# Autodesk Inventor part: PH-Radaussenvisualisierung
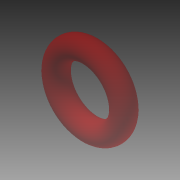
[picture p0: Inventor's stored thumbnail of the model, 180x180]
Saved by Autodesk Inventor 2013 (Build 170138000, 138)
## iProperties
Created: 2012-07
Part Number: PH-Radaussenvisualisierung
Material: Rot - Durchsichtig
Document SubType Name: Modeling
Designer: rYan
Mass: 13.8569 g
Surface Area: 46.1897 cm^2
Volume: 13.8569 cm^3
Density: 1 g/cm^3
Author: rYan
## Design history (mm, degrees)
sketch "Skizze1"
  geometry: L1 (-5.1, 0)-(30.6, 0) reference; L2 (0, -7.037)-(0, 7.017); L3 (0, 9.828)-(0, -9.848) reference; C1 r 6 at (19.5, 0); 1 further point
  constraints: 2 end point, 1 centre point, 1 collinear, 1 perpendicular, 1 point on line
  dimensions: "d0" = 12 diameter of C1; "d4" = 39 diameter of C1.centre L2
revolve "Umdrehung1" sketch "Skizze1" stored, may be unused: angle "d3" = 90 deg
node "Volumenkörper1"
